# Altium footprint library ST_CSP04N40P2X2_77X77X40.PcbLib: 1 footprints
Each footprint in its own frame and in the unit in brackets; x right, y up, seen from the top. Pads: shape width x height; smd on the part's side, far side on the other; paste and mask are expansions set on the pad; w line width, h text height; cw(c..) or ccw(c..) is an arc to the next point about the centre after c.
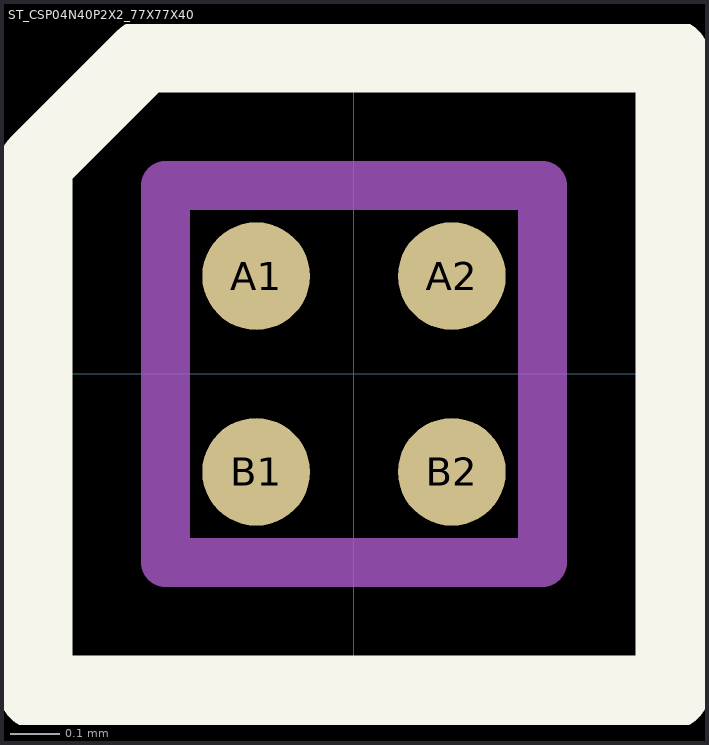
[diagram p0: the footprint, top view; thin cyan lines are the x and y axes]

## ST_CSP04N40P2X2_77X77X40 [mm] "CSP04N40P2X2_77X77X40"
height 0.45
pads (4):
  round 0.22 smd: A1(-0.2,0.2) A2(0.2,0.2) B1(-0.2,-0.2) B2(0.2,-0.2)
Top Overlay:
  lines w0.15: -0.65,-0.65 0.65,-0.65 0.65,0.65 -0.43,0.65 -0.65,0.43 -0.65,-0.65
Top Paste:
  rectangle: -0.31,-0.31 -0.09,-0.09
  rectangle: 0.09,-0.31 0.31,-0.09
  rectangle: 0.09,0.09 0.31,0.31
  rectangle: -0.31,0.09 -0.09,0.31
Mechanical 13:
  lines w0.1: -0.385,-0.385 -0.385,0.385 0.385,0.385 0.385,-0.385 -0.385,-0.385
3D body "ST_CSP04N40P2X2_77X77X40_.step": height 0.45, standoff 0, extent -0.385,-0.385 0.385,0.385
